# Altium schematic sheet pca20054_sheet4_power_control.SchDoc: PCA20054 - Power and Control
size A3; Organization: Nordic Semiconductor; DocumentNumber: 1; Revision: 1.0.0; SheetNumber: 4; SheetTotal: 5; Date: 2020-02-07; CompanyName: Nordic Semiconductor; DrawnBy: KJP; ProjectNumber: 4467
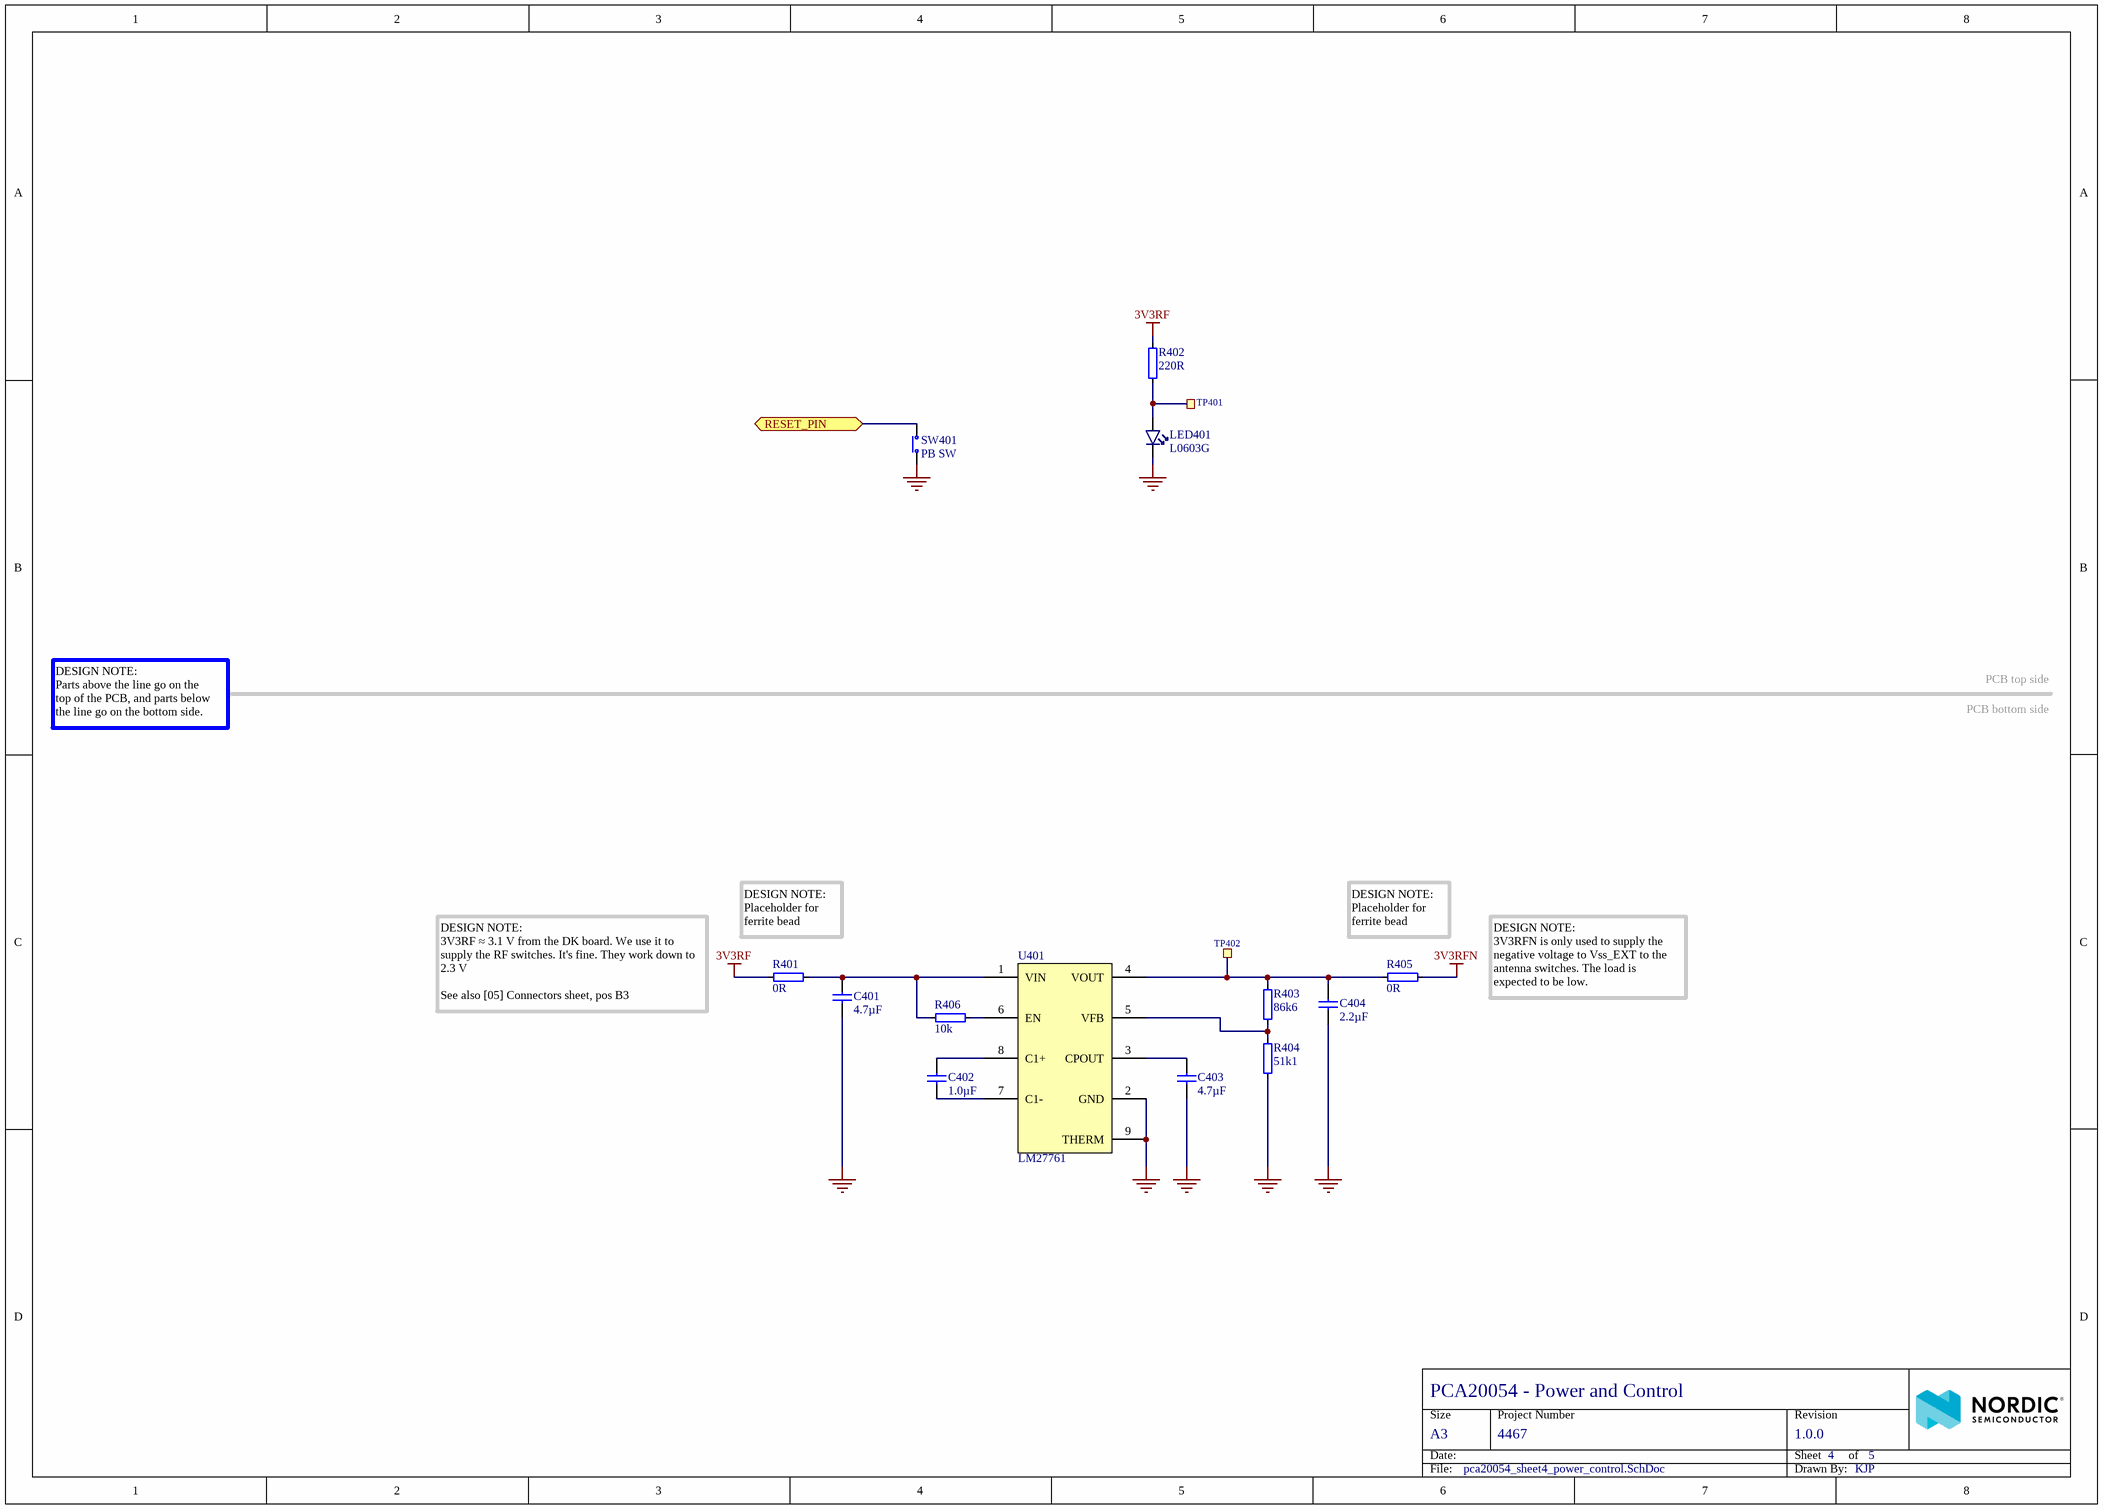
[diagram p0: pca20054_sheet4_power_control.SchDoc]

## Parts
C401  4.7µF  [CAPC1608X06L]
C402  1.0µF  [CAPC1608X06L]
C403  4.7µF  [CAPC1608X06L]
C404  2.2µF  [CAPC1608X06L]
LED401  L0603G  [LED_0603_G]
R401  0R  [RESC1005X04L]
R402  220R  [RESC1005X04L]
R403  86k6  [RESC1005X04L]
R404  51k1  [RESC1005X04L]
R405  0R  [RESC1005X04L]
R406  10k  [RESC1005X04L]
SW401  PB SW  [Switch-PB-6.2x6.3mm-SMD]
TP401  Ø1.0mm,SMD  [TP_SMD_Ø1.0mm]  (value not drawn)  (no BOM)
TP402  Ø1.0mm,SMD  [TP_SMD_Ø1.0mm]  (value not drawn)  (no BOM)
U401  LM27761  [SON50P200X80_HS-9L]

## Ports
RESET_PIN (bidir)

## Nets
3V3RF: R401.1 R402.2
3V3RFN: R405.2
GND: C401.1 C403.1 C404.1 LED401.1(C) R404.1 SW401.2(COM) U401.2(GND) U401.9(THERM)
RESET_PIN: SW401.1(N.O) ; port RESET_PIN
NetC401_2: C401.2 R401.2 R406.1 U401.1(VIN)
NetC402_1: C402.1 U401.7(C1-)
NetC402_2: C402.2 U401.8(C1+)
NetC403_2: C403.2 U401.3(CPOUT)
NetC404_2: C404.2 R403.2 R405.1 TP402.1 U401.4(VOUT)
NetLED401_2: LED401.2(A) R402.1 TP401.1
NetR403_1: R403.1 R404.2 U401.5(VFB)
NetR406_2: R406.2 U401.6(EN)

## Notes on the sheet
- DESIGN NOTE:
  Parts above the line go on the
  top of the PCB, and parts below
  the line go on the bottom side.
- PCB bottom side
- PCB top side
- DESIGN NOTE:
  Placeholder for ferrite bead
- (near R405) DESIGN NOTE:
  Placeholder for ferrite bead
- DESIGN NOTE:
  3V3RFN is only used to supply the
  negative voltage to Vss_EXT to the
  antenna switches. The load is
  expected to be low.
- DESIGN NOTE:
  3V3RF ≈ 3.1 V from the DK board. We use it to supply the RF switches. It's fine. They work down to 2.3 V
  See also [05] Connectors sheet, pos B3

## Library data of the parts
C401 C403 = C0603-4µ7: Capacitor, X5R, ±10%; Part number IPS: 00000007783; Note: 6.3V; Artikkelnr Noca: 20069060
C402 = C0603-1µ0: Capacitor, X7R, ±10%; Part number IPS: 00000000616; Note: 16V; Artikkelnr Noca: 20039282
C404 = C0603-2µ2: Capacitor, X7R, ±10%; Part number IPS: N.A.; Note: 6.3V; Artikkelnr Noca: 20039322
LED401 = LG L29K Smartled Green: LED, Green, 0603, 570nm, Vf=1.7V, 2.24..5.6mcd, - 40 to +100°C; Manufacturer: Osram; Manufacturer Part Number: LG L29K-G2J1-24-Z; Part number IPS: 00000009961; Note: 2.24..5.6 mcd, Vfmin=1.7V; Artikkelnr Noca: 13019147
R401 R405 = R0402-0R: Resistor, ±5%, 0.063W; Part number IPS: 00000007128; Note: Chip Res 5%; Artikkelnr Noca: 27049000
R402 = R0402-220: Resistor, ±1%, 0.063W; Part number IPS: N.A.; Note: Chip Res 1%; Artikkelnr Noca: 27049057
R403 = R0402-86k6: Resistor, ±1%, 0.063W; Manufacturer: Panasonic; Manufacturer Part Number: ERJ-2RKF8662X; Part number IPS: N.A.; Note: Chip Res 1%; Artikkelnr Noca: 27049119
R404 = R0402-51k1: Resistor, ±0.1%, 0.063W; Manufacturer: Panasonic; Manufacturer Part Number: ERA-2AEB5112X; Note: Chip Res 1%; Artikkelnr Noca: N.A.
R406 = R0402-10k: Resistor, ±1%, 0.063W; Part number IPS: 00000002093; Note: Chip Res 1%; Artikkelnr Noca: 27049097
SW401 = Switch-PB-6.2x6.3mm-SMD: Tactile Switch, SPNO, SMD, 160gf, 6.2x6.3x2.5mm; Manufacturer: Dailywell; Manufacturer Part Number: TS604VM1-025BR-R; Part number IPS: 00000007812; Artikkelnr Noca: 50019106
TP401 TP402 = TP_SMD_Ø1.0MM: 1.0mm circular SMD testpad; Manufacturer: Nordic Semiconductor; Artikkelnr Noca: N.A.
U401 = LM27761: Low-Noise, Regulated, Switched-Capacitor Voltage Inverter; Manufacturer: Texas Instruments; Note: DSGT: 250 pts reel; Artikkelnr Noca: N.A.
